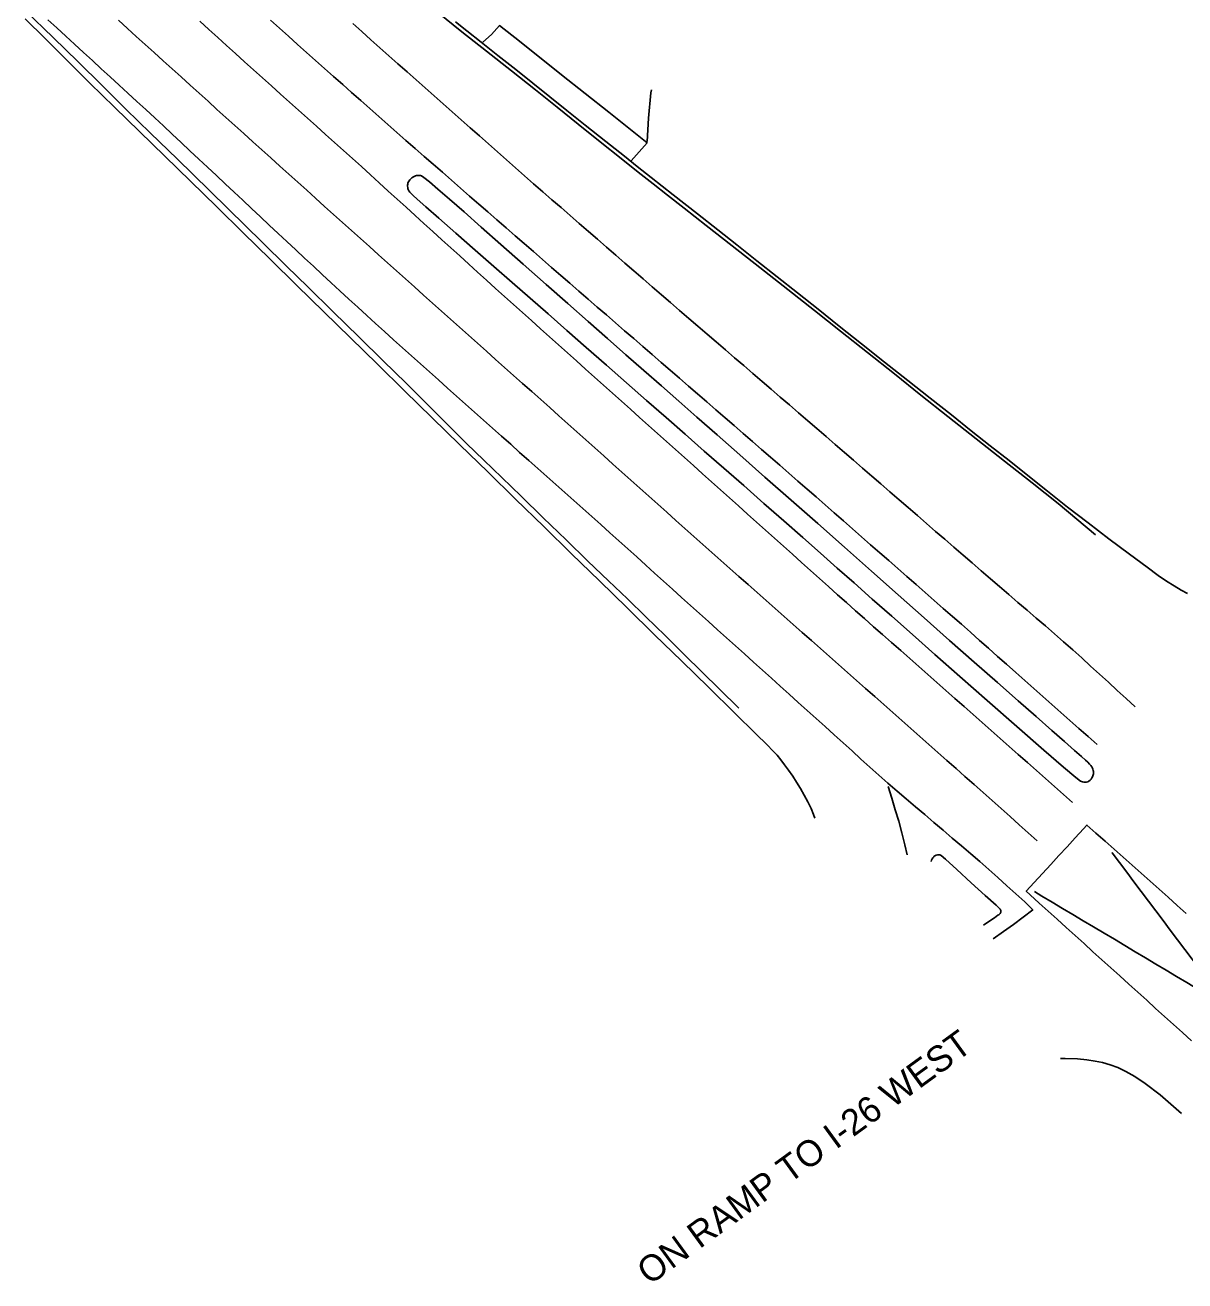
# Model space of a CAD drawing. Extents: x 1970211 to 1973046, y 801032 to 804001.
# Drawn here: x 1971113.3 to 1971353.3, y 802796.2 to 803056 of the extents above; entities that cross this region are included whole.
import ezdxf

# ---------------------------------------------------------------- set-up
doc = ezdxf.new("R2010")
doc.units = 0
for name, color, linetype in [('RD_EX_Conc', 7, 'Continuous'), ('RD_EX_Road', 7, 'Continuous'), ('RD_EX_Road_Paint', 7, 'Continuous'), ('RD_TX_RoadID', 7, 'Continuous')]:
    doc.layers.add(name, color=color, linetype=linetype)

msp = doc.modelspace()

# ---------------------------------------------------------------- linework, layer by layer
at = {"layer": 'RD_EX_Conc'}
for points in [[(1971113.29, 803057.35), (1971117.41, 803053.27), (1971121.85, 803048.86), (1971126.71, 803044.05), (1971131.8, 803039.05), (1971136.96, 803034.03), (1971142.2, 803028.95), (1971147.54, 803023.75), (1971152.97, 803018.45), (1971158.45, 803013.08), (1971163.98, 803007.65), (1971169.55, 803002.19), (1971175.11, 802996.73), (1971180.65, 802991.31), (1971186.21, 802985.87), (1971191.84, 802980.37), (1971197.52, 802974.82), (1971203.25, 802969.22), (1971209.02, 802963.61), (1971214.81, 802957.97), (1971220.61, 802952.33), (1971226.4, 802946.68), (1971232.16, 802941.06), (1971237.89, 802935.46), (1971243.57, 802929.91), (1971249.18, 802924.43), (1971254.72, 802919.03), (1971260.17, 802913.71), (1971264.55, 802909.42), (1971266.9, 802907.12), (1971268.07, 802905.92), (1971268.93, 802904.97), (1971269.67, 802904.06), (1971270.47, 802903.01), (1971271.31, 802901.86), (1971272.15, 802900.65), (1971272.96, 802899.38), (1971273.74, 802898.08), (1971274.51, 802896.73), (1971275.28, 802895.31), (1971275.97, 802893.93), (1971276.48, 802892.72), (1971276.74, 802891.99)], [(1971202.38, 803056.74), (1971204.73, 803054.86), (1971207.67, 803052.53), (1971211.15, 803049.77), (1971214.83, 803046.84), (1971218.37, 803044.03), (1971221.87, 803041.24), (1971225.42, 803038.38), (1971229.23, 803035.33), (1971233.47, 803031.96), (1971237.33, 803028.91), (1971239.99, 803026.82), (1971242.89, 803024.54), (1971247.43, 803020.96), (1971252.43, 803017.02), (1971256.66, 803013.68), (1971260.6, 803010.56), (1971264.75, 803007.29), (1971268.97, 803003.96), (1971273.15, 803000.66), (1971277.39, 802997.29), (1971281.8, 802993.77), (1971286.4, 802990.11), (1971291.18, 802986.33), (1971295.97, 802982.54), (1971300.6, 802978.87), (1971305, 802975.38), (1971309.11, 802972.13), (1971313.04, 802969.01), (1971316.92, 802965.95), (1971320.83, 802962.85), (1971324.88, 802959.63), (1971329.05, 802956.34), (1971333.3, 802953.03), (1971337.58, 802949.77), (1971341.86, 802946.59), (1971345.48, 802943.92), (1971347.82, 802942.19), (1971349.49, 802941.02), (1971351.09, 802940), (1971352.57, 802939.14), (1971353.88, 802938.45)], [(1971238.73, 803027.94), (1971239.85, 803029.19), (1971242.01, 803031.7), (1971234.07, 803038.04), (1971224.31, 803045.79), (1971215.58, 803052.73), (1971211.5, 803055.94), (1971209.83, 803054.13), (1971208, 803052.52)], [(1971192.76, 803023.84), (1971192.63, 803023.63), (1971192.53, 803023.41), (1971192.47, 803023.17), (1971192.45, 803022.94), (1971192.45, 803022.7), (1971192.47, 803022.47), (1971192.51, 803022.24), (1971192.57, 803022.02), (1971192.68, 803021.79), (1971192.88, 803021.51), (1971193.18, 803021.18), (1971193.57, 803020.8), (1971194.45, 803020.02), (1971196.23, 803018.45), (1971198.9, 803016.11), (1971202.46, 803012.99), (1971206.43, 803009.51), (1971210.31, 803006.12), (1971214.1, 803002.8), (1971217.8, 802999.55), (1971221.52, 802996.28), (1971225.4, 802992.88), (1971229.42, 802989.36), (1971233.58, 802985.71), (1971237.78, 802982.02), (1971241.9, 802978.41), (1971245.94, 802974.87), (1971249.9, 802971.39), (1971253.86, 802967.92), (1971257.9, 802964.37), (1971262.01, 802960.76), (1971266.2, 802957.09), (1971270.31, 802953.47), (1971274.22, 802950.03), (1971277.9, 802946.78), (1971281.38, 802943.71), (1971284.88, 802940.62), (1971288.63, 802937.29), (1971292.65, 802933.74), (1971296.92, 802929.95), (1971301.58, 802925.83), (1971306.73, 802921.29), (1971312.38, 802916.33), (1971318.52, 802910.95), (1971324.14, 802906.04), (1971328.21, 802902.52), (1971330.73, 802900.37), (1971331.69, 802899.6), (1971331.9, 802899.53), (1971332.12, 802899.47), (1971332.38, 802899.43), (1971332.66, 802899.4), (1971332.94, 802899.4), (1971333.21, 802899.48), (1971333.47, 802899.61), (1971333.71, 802899.82), (1971333.92, 802900.05), (1971334.08, 802900.27), (1971334.21, 802900.49), (1971334.3, 802900.7), (1971334.35, 802900.91), (1971334.38, 802901.13), (1971334.4, 802901.36), (1971334.39, 802901.6), (1971334.36, 802901.84), (1971334.29, 802902.08), (1971334.19, 802902.32), (1971334.06, 802902.56), (1971333.86, 802902.83), (1971333.57, 802903.16), (1971333.2, 802903.54), (1971332.73, 802903.98), (1971331.91, 802904.71), (1971330.47, 802905.98), (1971328.43, 802907.79), (1971325.76, 802910.13), (1971322.54, 802912.96), (1971318.79, 802916.26), (1971314.52, 802920.02), (1971309.74, 802924.23), (1971304.62, 802928.75), (1971299.36, 802933.39), (1971293.97, 802938.16), (1971288.43, 802943.06), (1971282.85, 802948), (1971277.32, 802952.9), (1971271.83, 802957.74), (1971266.39, 802962.54), (1971261.22, 802967.1), (1971256.52, 802971.24), (1971252.29, 802974.96), (1971248.55, 802978.25), (1971244.99, 802981.38), (1971241.36, 802984.58), (1971237.63, 802987.85), (1971233.83, 802991.2), (1971229.85, 802994.7), (1971225.61, 802998.43), (1971221.12, 803002.4), (1971216.37, 803006.61), (1971211.76, 803010.68), (1971207.68, 803014.27), (1971204.14, 803017.38), (1971201.14, 803020), (1971198.73, 803022.09), (1971196.96, 803023.6), (1971195.83, 803024.52), (1971195.33, 803024.87), (1971195.15, 803024.92), (1971194.95, 803024.95), (1971194.74, 803024.96), (1971194.52, 803024.96), (1971194.29, 803024.92), (1971194.05, 803024.85), (1971193.8, 803024.75), (1971193.55, 803024.6), (1971193.31, 803024.43), (1971193.1, 803024.25), (1971192.92, 803024.05), (1971192.76, 803023.84)], [(1971311.66, 802869.84), (1971312.71, 802870.56), (1971313.9, 802871.36), (1971314.64, 802871.86), (1971314.84, 802871.99), (1971314.96, 802872.09), (1971315.06, 802872.22), (1971315.14, 802872.37), (1971315.2, 802872.53), (1971315.23, 802872.7), (1971315.22, 802872.86), (1971315.18, 802872.99), (1971315.1, 802873.12), (1971314.24, 802873.94), (1971312.01, 802875.95), (1971309.08, 802878.59), (1971306.11, 802881.32), (1971303.8, 802883.44), (1971302.86, 802884.26), (1971302.73, 802884.33), (1971302.6, 802884.38), (1971302.47, 802884.4), (1971302.35, 802884.4), (1971302.09, 802884.36), (1971301.83, 802884.29), (1971301.7, 802884.23), (1971301.58, 802884.17), (1971301.46, 802884.09), (1971301.36, 802883.99), (1971301.18, 802883.78), (1971301.04, 802883.55), (1971300.91, 802883.3), (1971300.79, 802883.01)], [(1971352.65, 802830.85), (1971348.17, 802834.7), (1971345.13, 802837.06), (1971342.96, 802838.49), (1971341.12, 802839.56), (1971339.46, 802840.35), (1971337.84, 802840.95), (1971336.26, 802841.39), (1971334.73, 802841.71), (1971333.06, 802841.96), (1971331.08, 802842.18), (1971328.55, 802842.26), (1971327.59, 802842.23)]]:
    msp.add_lwpolyline(points, dxfattribs=at)
at = {"layer": 'RD_EX_Road'}
for points in [[(1971260.98, 802914.75), (1971257.01, 802918.67), (1971253.44, 802922.18), (1971249.71, 802925.84), (1971245.73, 802929.73), (1971241.73, 802933.63), (1971237.93, 802937.32), (1971234.05, 802941.06), (1971229.78, 802945.15), (1971225.24, 802949.53), (1971220.52, 802954.13), (1971215.97, 802958.58), (1971211.92, 802962.47), (1971208.2, 802966.04), (1971204.64, 802969.5), (1971200.91, 802973.19), (1971196.68, 802977.39), (1971192.12, 802981.93), (1971187.41, 802986.6), (1971182.41, 802991.51), (1971177, 802996.79), (1971171.79, 803001.88), (1971167.4, 803006.18), (1971162.4, 803011.1), (1971155.34, 803018.02), (1971151.46, 803021.81), (1971144.74, 803028.36), (1971139.26, 803033.69), (1971134.16, 803038.69), (1971129.24, 803043.56), (1971124.25, 803048.46), (1971119.09, 803053.5), (1971113.4, 803059.02)], [(1971198.61, 803058.71), (1971203.7, 803054.68), (1971208.78, 803050.66), (1971213.94, 803046.58), (1971218.9, 803042.64), (1971223.38, 803039.06), (1971227.74, 803035.57), (1971232.33, 803031.88), (1971236.65, 803028.42), (1971240.19, 803025.61), (1971243.28, 803023.18), (1971246.22, 803020.88), (1971249.66, 803018.18), (1971254.25, 803014.59), (1971259.61, 803010.4), (1971265.38, 803005.89), (1971271.17, 803001.33), (1971276.64, 802997), (1971282.04, 802992.72), (1971287.63, 802988.3), (1971293.24, 802983.86), (1971298.7, 802979.51), (1971304.24, 802975.1), (1971310.09, 802970.47), (1971315.99, 802965.82), (1971321.72, 802961.33), (1971327.11, 802957.07), (1971334.83, 802950.59)], [(1971242.05, 803031.98), (1971242.28, 803036.79), (1971242.8, 803042.01), (1971242.9, 803042.63)]]:
    msp.add_lwpolyline(points, dxfattribs=at)
at = {"layer": 'RD_EX_Road_Paint'}
for points in [[(1971313.62, 802867.02), (1971315.78, 802868.52), (1971317.84, 802869.94), (1971319.83, 802871.45), (1971321.82, 802872.97), (1971320.18, 802874.63), (1971318.33, 802876.31), (1971316.47, 802877.98), (1971314.62, 802879.66), (1971312.76, 802881.34), (1971310.89, 802882.99), (1971308.99, 802884.61), (1971307.08, 802886.22), (1971305.18, 802887.84), (1971303.28, 802889.46), (1971301.37, 802891.08), (1971299.47, 802892.7), (1971297.56, 802894.32), (1971295.66, 802895.93), (1971293.76, 802897.55), (1971291.85, 802899.17), (1971289.99, 802900.84), (1971288.14, 802902.51), (1971286.28, 802904.19), (1971284.43, 802905.86), (1971282.58, 802907.54), (1971280.72, 802909.21), (1971278.87, 802910.89), (1971277.01, 802912.56), (1971275.16, 802914.24), (1971273.3, 802915.91), (1971271.45, 802917.58), (1971269.59, 802919.25), (1971267.73, 802920.92), (1971265.87, 802922.59), (1971264.01, 802924.26), (1971262.15, 802925.93), (1971260.29, 802927.6), (1971258.44, 802929.28), (1971256.58, 802930.95), (1971254.72, 802932.62), (1971252.86, 802934.29), (1971251, 802935.96), (1971249.15, 802937.63), (1971247.29, 802939.31), (1971245.44, 802940.98), (1971243.58, 802942.65), (1971241.72, 802944.32), (1971239.87, 802946), (1971238.01, 802947.67), (1971236.15, 802949.34), (1971234.3, 802951.02), (1971232.44, 802952.69), (1971230.57, 802954.35), (1971228.71, 802956.01), (1971226.84, 802957.68), (1971224.97, 802959.34), (1971223.11, 802961), (1971221.24, 802962.66), (1971219.38, 802964.32), (1971217.51, 802965.99), (1971215.64, 802967.65), (1971213.78, 802969.31), (1971211.91, 802970.97), (1971210.05, 802972.64), (1971208.18, 802974.3), (1971206.31, 802975.96), (1971204.45, 802977.63), (1971202.58, 802979.29), (1971200.72, 802980.95), (1971198.85, 802982.62), (1971196.99, 802984.28), (1971195.12, 802985.94), (1971193.26, 802987.61), (1971191.39, 802989.27), (1971189.54, 802990.95), (1971187.68, 802992.62), (1971185.83, 802994.3), (1971183.98, 802995.98), (1971182.13, 802997.66), (1971180.28, 802999.34), (1971178.45, 803001.04), (1971176.62, 803002.74), (1971174.78, 803004.44), (1971172.95, 803006.14), (1971171.12, 803007.85), (1971169.29, 803009.55), (1971167.47, 803011.26), (1971165.64, 803012.96), (1971163.81, 803014.67), (1971161.99, 803016.38), (1971160.16, 803018.09), (1971158.34, 803019.8), (1971156.52, 803021.51), (1971154.69, 803023.22), (1971152.87, 803024.93), (1971151.05, 803026.63), (1971149.22, 803028.34), (1971147.4, 803030.05), (1971145.57, 803031.76), (1971143.75, 803033.47), (1971141.93, 803035.18), (1971140.1, 803036.89), (1971138.26, 803038.58), (1971136.42, 803040.27), (1971134.58, 803041.96), (1971132.74, 803043.65), (1971130.89, 803045.34), (1971129.05, 803047.03), (1971127.21, 803048.72), (1971125.37, 803050.41), (1971123.52, 803052.1), (1971121.68, 803053.79), (1971119.84, 803055.48), (1971117.99, 803057.16)], [(1971322.75, 802887.29), (1971320.88, 802888.95), (1971319.02, 802890.61), (1971317.15, 802892.27), (1971315.28, 802893.93), (1971313.41, 802895.59), (1971311.55, 802897.25), (1971309.68, 802898.91), (1971307.81, 802900.57), (1971305.95, 802902.23), (1971304.08, 802903.89), (1971302.21, 802905.55), (1971300.34, 802907.21), (1971298.48, 802908.87), (1971296.61, 802910.53), (1971294.74, 802912.19), (1971292.87, 802913.84), (1971291, 802915.5), (1971289.12, 802917.16), (1971287.25, 802918.81), (1971285.38, 802920.47), (1971283.51, 802922.12), (1971281.64, 802923.78), (1971279.77, 802925.44), (1971277.89, 802927.09), (1971276.02, 802928.74), (1971274.14, 802930.39), (1971272.27, 802932.05), (1971270.4, 802933.7), (1971268.52, 802935.35), (1971266.65, 802937.01), (1971264.77, 802938.66), (1971262.9, 802940.31), (1971261.03, 802941.97), (1971259.15, 802943.62), (1971257.28, 802945.27), (1971255.4, 802946.93), (1971253.53, 802948.58), (1971251.66, 802950.24), (1971249.8, 802951.9), (1971247.93, 802953.57), (1971246.07, 802955.24), (1971244.21, 802956.9), (1971242.35, 802958.57), (1971240.48, 802960.24), (1971238.62, 802961.9), (1971236.76, 802963.57), (1971234.9, 802965.23), (1971233.03, 802966.9), (1971231.17, 802968.57), (1971229.31, 802970.23), (1971227.45, 802971.9), (1971225.58, 802973.57), (1971223.72, 802975.23), (1971221.86, 802976.9), (1971219.99, 802978.56), (1971218.13, 802980.23), (1971216.26, 802981.89), (1971214.4, 802983.56), (1971212.53, 802985.22), (1971210.67, 802986.89), (1971208.81, 802988.55), (1971206.94, 802990.21), (1971205.08, 802991.88), (1971203.21, 802993.54), (1971201.35, 802995.21), (1971199.48, 802996.87), (1971197.62, 802998.54), (1971195.76, 803000.2), (1971193.89, 803001.87), (1971192.03, 803003.53), (1971190.17, 803005.2), (1971188.31, 803006.87), (1971186.44, 803008.54), (1971184.58, 803010.21), (1971182.72, 803011.87), (1971180.86, 803013.54), (1971179, 803015.21), (1971177.14, 803016.88), (1971175.28, 803018.55), (1971173.42, 803020.22), (1971171.56, 803021.89), (1971169.7, 803023.56), (1971167.84, 803025.22), (1971165.98, 803026.89), (1971164.12, 803028.56), (1971162.26, 803030.24), (1971160.41, 803031.92), (1971158.55, 803033.59), (1971156.7, 803035.27), (1971154.84, 803036.94), (1971152.99, 803038.62), (1971151.14, 803040.3), (1971149.28, 803041.97), (1971147.43, 803043.65), (1971145.57, 803045.33), (1971143.72, 803047), (1971141.86, 803048.68), (1971140.01, 803050.35), (1971138.16, 803052.03), (1971136.3, 803053.71), (1971134.45, 803055.38), (1971132.6, 803057.06)], [(1971335.15, 802907.23), (1971333.27, 802908.88), (1971331.4, 802910.54), (1971329.53, 802912.19), (1971327.66, 802913.85), (1971325.79, 802915.51), (1971323.92, 802917.16), (1971322.05, 802918.82), (1971320.18, 802920.47), (1971318.3, 802922.13), (1971316.43, 802923.79), (1971314.56, 802925.44), (1971312.69, 802927.1), (1971310.82, 802928.75), (1971308.95, 802930.41), (1971307.08, 802932.07), (1971305.2, 802933.71), (1971303.32, 802935.36), (1971301.44, 802937.01), (1971299.56, 802938.65), (1971297.68, 802940.3), (1971295.8, 802941.95), (1971293.92, 802943.59), (1971292.04, 802945.24), (1971290.16, 802946.89), (1971288.28, 802948.53), (1971286.4, 802950.18), (1971284.52, 802951.83), (1971282.64, 802953.47), (1971280.76, 802955.12), (1971278.88, 802956.77), (1971277, 802958.41), (1971275.12, 802960.06), (1971273.24, 802961.7), (1971271.36, 802963.35), (1971269.48, 802964.99), (1971267.59, 802966.63), (1971265.7, 802968.27), (1971263.81, 802969.9), (1971261.92, 802971.54), (1971260.04, 802973.18), (1971258.15, 802974.81), (1971256.26, 802976.45), (1971254.37, 802978.09), (1971252.48, 802979.73), (1971250.6, 802981.36), (1971248.71, 802983), (1971246.82, 802984.63), (1971244.93, 802986.27), (1971243.04, 802987.9), (1971241.15, 802989.54), (1971239.26, 802991.18), (1971237.37, 802992.81), (1971235.48, 802994.45), (1971233.59, 802996.08), (1971231.7, 802997.72), (1971229.81, 802999.35), (1971227.92, 803000.99), (1971226.03, 803002.63), (1971224.14, 803004.27), (1971222.26, 803005.91), (1971220.37, 803007.55), (1971218.49, 803009.19), (1971216.6, 803010.83), (1971214.71, 803012.47), (1971212.83, 803014.11), (1971210.94, 803015.75), (1971209.06, 803017.39), (1971207.17, 803019.03), (1971205.29, 803020.67), (1971203.41, 803022.32), (1971201.52, 803023.96), (1971199.64, 803025.61), (1971197.76, 803027.25), (1971195.88, 803028.89), (1971193.99, 803030.54), (1971192.11, 803032.18), (1971190.23, 803033.83), (1971188.35, 803035.48), (1971186.48, 803037.14), (1971184.61, 803038.8), (1971182.74, 803040.46), (1971180.87, 803042.12), (1971179.01, 803043.77), (1971177.14, 803045.43), (1971175.27, 803047.09), (1971173.4, 803048.75), (1971171.53, 803050.41), (1971169.66, 803052.07), (1971167.79, 803053.73), (1971165.92, 803055.39), (1971164.05, 803057.05)], [(1971330.08, 802895.18), (1971328.21, 802896.84), (1971326.34, 802898.49), (1971324.46, 802900.15), (1971322.59, 802901.8), (1971320.72, 802903.46), (1971318.84, 802905.11), (1971316.97, 802906.76), (1971315.1, 802908.42), (1971313.23, 802910.07), (1971311.35, 802911.73), (1971309.48, 802913.38), (1971307.61, 802915.04), (1971305.73, 802916.69), (1971303.86, 802918.35), (1971301.99, 802920), (1971300.12, 802921.66), (1971298.24, 802923.31), (1971296.37, 802924.97), (1971294.5, 802926.62), (1971292.63, 802928.27), (1971290.76, 802929.93), (1971288.88, 802931.58), (1971287.01, 802933.24), (1971285.14, 802934.89), (1971283.27, 802936.55), (1971281.39, 802938.2), (1971279.53, 802939.87), (1971277.67, 802941.54), (1971275.81, 802943.21), (1971273.95, 802944.88), (1971272.09, 802946.55), (1971270.23, 802948.22), (1971268.37, 802949.89), (1971266.51, 802951.56), (1971264.65, 802953.23), (1971262.79, 802954.89), (1971260.93, 802956.56), (1971259.07, 802958.23), (1971257.21, 802959.9), (1971255.35, 802961.57), (1971253.49, 802963.23), (1971251.62, 802964.9), (1971249.76, 802966.57), (1971247.9, 802968.23), (1971246.03, 802969.9), (1971244.17, 802971.56), (1971242.31, 802973.23), (1971240.44, 802974.89), (1971238.58, 802976.56), (1971236.72, 802978.22), (1971234.85, 802979.89), (1971232.99, 802981.56), (1971231.13, 802983.22), (1971229.27, 802984.89), (1971227.41, 802986.56), (1971225.55, 802988.23), (1971223.69, 802989.9), (1971221.82, 802991.56), (1971219.96, 802993.23), (1971218.1, 802994.9), (1971216.24, 802996.57), (1971214.38, 802998.24), (1971212.52, 802999.91), (1971210.66, 803001.57), (1971208.8, 803003.24), (1971206.94, 803004.91), (1971205.09, 803006.6), (1971203.24, 803008.28), (1971201.39, 803009.96), (1971199.54, 803011.64), (1971197.69, 803013.32), (1971195.84, 803015), (1971193.99, 803016.68), (1971192.14, 803018.36), (1971190.29, 803020.04), (1971188.44, 803021.72), (1971186.59, 803023.4), (1971184.74, 803025.08), (1971182.89, 803026.76), (1971181.03, 803028.44), (1971179.17, 803030.11), (1971177.31, 803031.77), (1971175.45, 803033.44), (1971173.59, 803035.11), (1971171.73, 803036.78), (1971169.87, 803038.45), (1971168.01, 803040.12), (1971166.15, 803041.79), (1971164.29, 803043.46), (1971162.43, 803045.13), (1971160.57, 803046.8), (1971158.71, 803048.47), (1971156.85, 803050.14), (1971155, 803051.82), (1971153.14, 803053.49), (1971151.29, 803055.17), (1971149.44, 803056.85)], [(1971343.02, 802915.01), (1971341.18, 802916.7), (1971339.33, 802918.39), (1971337.49, 802920.07), (1971335.65, 802921.76), (1971333.8, 802923.44), (1971331.96, 802925.13), (1971330.12, 802926.82), (1971328.23, 802928.46), (1971326.34, 802930.09), (1971324.44, 802931.72), (1971322.55, 802933.35), (1971320.66, 802934.98), (1971318.76, 802936.61), (1971316.87, 802938.24), (1971314.98, 802939.87), (1971313.08, 802941.5), (1971311.19, 802943.13), (1971309.29, 802944.76), (1971307.4, 802946.39), (1971305.51, 802948.03), (1971303.62, 802949.66), (1971301.73, 802951.3), (1971299.84, 802952.93), (1971297.95, 802954.57), (1971296.06, 802956.21), (1971294.17, 802957.84), (1971292.28, 802959.48), (1971290.39, 802961.11), (1971288.51, 802962.75), (1971286.62, 802964.38), (1971284.73, 802966.02), (1971282.84, 802967.65), (1971280.95, 802969.29), (1971279.06, 802970.93), (1971277.17, 802972.56), (1971275.28, 802974.19), (1971273.38, 802975.82), (1971271.49, 802977.45), (1971269.59, 802979.08), (1971267.7, 802980.71), (1971265.8, 802982.34), (1971263.91, 802983.97), (1971262.01, 802985.6), (1971260.12, 802987.23), (1971258.22, 802988.86), (1971256.33, 802990.49), (1971254.43, 802992.12), (1971252.54, 802993.74), (1971250.64, 802995.37), (1971248.75, 802997), (1971246.86, 802998.64), (1971244.97, 803000.27), (1971243.08, 803001.91), (1971241.19, 803003.55), (1971239.3, 803005.19), (1971237.41, 803006.82), (1971235.53, 803008.46), (1971233.64, 803010.1), (1971231.75, 803011.73), (1971229.86, 803013.37), (1971227.97, 803015.01), (1971226.08, 803016.65), (1971224.2, 803018.28), (1971222.31, 803019.92), (1971220.42, 803021.56), (1971218.53, 803023.2), (1971216.65, 803024.84), (1971214.78, 803026.5), (1971212.91, 803028.15), (1971211.04, 803029.81), (1971209.17, 803031.47), (1971207.3, 803033.13), (1971205.42, 803034.79), (1971203.55, 803036.44), (1971201.68, 803038.1), (1971199.81, 803039.76), (1971197.94, 803041.42), (1971196.07, 803043.08), (1971194.2, 803044.74), (1971192.33, 803046.39), (1971190.46, 803048.05), (1971188.59, 803049.71), (1971186.72, 803051.37), (1971184.86, 803053.03), (1971182.99, 803054.7), (1971181.13, 803056.36)], [(1971291.93, 802898.48), (1971292.66, 802896.09), (1971293.39, 802893.7), (1971294.13, 802891.31), (1971294.76, 802888.9), (1971295.35, 802886.47), (1971295.85, 802884.38)], [(1971354.69, 802845.9), (1971352.84, 802847.58), (1971350.98, 802849.25), (1971349.13, 802850.93), (1971347.27, 802852.6), (1971345.42, 802854.28), (1971343.57, 802855.95), (1971341.71, 802857.63), (1971339.86, 802859.31), (1971338.01, 802860.98), (1971336.15, 802862.66), (1971334.3, 802864.33), (1971332.45, 802866.01), (1971330.59, 802867.69), (1971328.74, 802869.36), (1971326.88, 802871.04), (1971325.03, 802872.71), (1971323.18, 802874.39), (1971321.32, 802876.06), (1971320.47, 802876.83), (1971322.16, 802878.68), (1971323.85, 802880.52), (1971325.55, 802882.36), (1971327.24, 802884.2), (1971328.93, 802886.04), (1971330.62, 802887.88), (1971332.31, 802889.72), (1971333.05, 802890.53), (1971334.92, 802888.87), (1971336.79, 802887.21), (1971338.65, 802885.55), (1971340.52, 802883.89), (1971342.39, 802882.23), (1971344.25, 802880.56), (1971346.12, 802878.9), (1971347.99, 802877.24), (1971349.85, 802875.58), (1971351.72, 802873.92), (1971353.59, 802872.26)], [(1971362.33, 802852.81), (1971360.82, 802854.8), (1971359.32, 802856.8), (1971357.82, 802858.79), (1971356.31, 802860.79), (1971354.81, 802862.79), (1971353.31, 802864.78), (1971351.8, 802866.78), (1971350.3, 802868.78), (1971348.79, 802870.77), (1971347.29, 802872.77), (1971345.79, 802874.76), (1971344.28, 802876.76), (1971342.78, 802878.76), (1971341.28, 802880.75), (1971339.77, 802882.75), (1971338.27, 802884.75), (1971338.19, 802884.85)], [(1971362.33, 802852.81), (1971360.18, 802854.09), (1971358.03, 802855.37), (1971355.89, 802856.65), (1971353.74, 802857.93), (1971351.6, 802859.21), (1971349.45, 802860.49), (1971347.3, 802861.77), (1971345.16, 802863.05), (1971343.01, 802864.33), (1971340.87, 802865.61), (1971338.72, 802866.89), (1971336.58, 802868.17), (1971334.43, 802869.45), (1971332.28, 802870.73), (1971330.14, 802872.01), (1971327.99, 802873.29), (1971325.85, 802874.57), (1971323.7, 802875.85), (1971322.18, 802876.76)]]:
    msp.add_lwpolyline(points, dxfattribs=at)

# ---------------------------------------------------------------- texts
at = {"layer": 'RD_TX_RoadID'}
msp.add_text('ON RAMP TO I-26 WEST', height=5.4, rotation=36.0649, dxfattribs=at).set_placement((1971242.5, 802795.19))

doc.saveas('drawing.dxf')
